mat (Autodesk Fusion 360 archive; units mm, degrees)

design "version 2" references "dumbell"
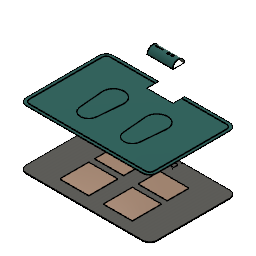
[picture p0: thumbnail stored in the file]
sketch "Sketch1"
  line L1 (808.1915, 45.9253) -> (8.1915, 45.9253)
  line L2 (858.1915, -504.0747) -> (858.1915, -4.0747)
  line L3 (8.1915, -554.0747) -> (808.1915, -554.0747)
  line L4 (-41.8085, -4.0747) -> (-41.8085, -504.0747)
  line L5 (408.1915, -554.0747) -> (408.1915, 45.9253)
  line L6 (858.1915, -254.0747) -> (-41.8085, -254.0747)
  line L7 (258.1915, -554.0747) -> (258.1915, 45.9253)
  line L8 (558.1915, -554.0747) -> (558.1915, 45.9253)
  line L9 (808.1915, 25.2382) -> (8.1915, 25.2382)
  line L10 (-21.1214, -4.0747) -> (-21.1214, -504.0747)
  line L11 (8.1915, -533.3876) -> (808.1915, -533.3876)
  line L12 (837.5044, -504.0747) -> (837.5044, -4.0747)
  arc A1 centre (8.1915, -4.0747) radius 50 clockwise from (-41.8085, -4.0747) to (8.1915, 45.9253)
  arc A2 centre (8.1915, -504.0747) radius 50 clockwise from (8.1915, -554.0747) to (-41.8085, -504.0747)
  arc A3 centre (808.1915, -504.0747) radius 50 clockwise from (858.1915, -504.0747) to (808.1915, -554.0747)
  arc A4 centre (808.1915, -4.0747) radius 50 clockwise from (808.1915, 45.9253) to (858.1915, -4.0747)
  arc A5 centre (808.1915, -4.0747) radius 29.3129 clockwise from (808.1915, 25.2382) to (837.5044, -4.0747)
  arc A6 centre (8.1915, -4.0747) radius 29.3129 clockwise from (-21.1214, -4.0747) to (8.1915, 25.2382)
  arc A7 centre (8.1915, -504.0747) radius 29.3129 clockwise from (8.1915, -533.3876) to (-21.1214, -504.0747)
  arc A8 centre (808.1915, -504.0747) radius 29.3129 clockwise from (837.5044, -504.0747) to (808.1915, -533.3876)
  point P2 (-41.8085, 45.9253)
  point P4 (-41.8085, -554.0747)
  point P3 (858.1915, 45.9253)
  dimension "d1" distance P2 P4 = 600
  dimension "d2" distance P2 P3 = 900
  dimension "d3" distance L4 L7 = 300
  dimension "d4" distance L7 L8 = 300
  dimension "d5" radius A1 = 50
  dimension "d6" radius A2 = 50
  dimension "d7" radius A3 = 50
  dimension "d8" radius A4 = 50
  dimension "d180" = 20.6871
work_plane "WorkPlane2" sketch "Sketch1" AlongDistance 10
sketch "Sketch3" plane through (408.1915, -254.0747, 10) normal (0, 0, 1) x axis (1, 0, 0)
  line L1 (-450, 250) -> (-450, -250)
  line L2 (400, 300) -> (-400, 300)
  line L3 (450, -250) -> (450, 250)
  line L4 (-400, -300) -> (400, -300)
  line L5 (0, -300) -> (0, 300)
  line L6 (90, 300) -> (-90, 300)
  line L7 (90, 220) -> (90, 300)
  line L8 (-90, 220) -> (90, 220)
  line L9 (-90, 300) -> (-90, 220)
  line L10 (90, 260) -> (-90, 260)
  line L11 (-41.3, 265) -> (-75, 265)
  line L12 (-41.3, 233) -> (-41.3, 265)
  line L13 (-75, 233) -> (-41.3, 233)
  line L14 (-75, 265) -> (-75, 233)
  line L15 (-37.7, 288.3) -> (-75, 288.3)
  line L16 (-37.7, 272) -> (-37.7, 288.3)
  line L17 (-75, 272) -> (-37.7, 272)
  line L18 (-75, 288.3) -> (-75, 272)
  line L19 (10.4, 265) -> (-21.3, 265)
  line L20 (10.4, 240.5) -> (10.4, 265)
  line L21 (-21.3, 240.5) -> (10.4, 240.5)
  line L22 (-21.3, 265) -> (-21.3, 240.5)
  line L23 (73, 240.5) -> (49.3, 240.5)
  line L24 (73, 272.5) -> (73, 240.5)
  line L25 (49.3, 272.5) -> (73, 272.5)
  line L26 (49.3, 240.5) -> (49.3, 272.5)
  arc A1 centre (-400, 250) radius 50 clockwise from (-450, 250) to (-400, 300)
  arc A2 centre (400, 250) radius 50 clockwise from (400, 300) to (450, 250)
  arc A3 centre (400, -250) radius 50 clockwise from (450, -250) to (400, -300)
  arc A4 centre (-400, -250) radius 50 clockwise from (-400, -300) to (-450, -250)
  point P24 (-90, 300)
  point P27 (-90, 220)
  point P30 (-75, 265)
  point P33 (-75, 233)
  point P34 (-75, 288.3)
  point P37 (-75, 272)
  point P35 (-37.7, 288.3)
  point P42 (49.3, 240.5)
  point P43 (73, 240.5)
  point P26 (90, 220)
  dimension "d19" distance P24 P27 = 80
  dimension "d21" distance L5 L7 = 90 (= "d38 / 2")
  dimension "d23" distance P30 P33 = 32
  dimension "d25" distance L8 L13 = 13
  dimension "d26" distance P34 P37 = 16.3
  dimension "d27" distance P34 P35 = 37.3
  dimension "d28" distance L11 L17 = 7
  dimension "d31" distance L12 L22 = 20
  dimension "d32" distance P42 P43 = 23.7
  dimension "d38" distance P26 P27 = 180
extrude "Extrude1" new body sketch "Sketch1" profile of L1 L2 L3 L4 A1 A2 A3 A4 blind -3
work_plane "WorkPlane3" sketch "Sketch3" AlongDistance 100
sketch "Sketch4" plane through (408.1915, 5.9253, 110) normal (0, 0, 1) x axis (1, 0, 0)
  line L1 (-90, -40) -> (90, -40)
  line L2 (90, -40) -> (90, 40)
  line L3 (-90, 40) -> (-90, -40)
  line L4 (90, 40) -> (-90, 40)
  line L5 (-75, -27) -> (-41.3, -27)
  line L6 (-75, 5) -> (-75, -27)
  line L7 (-75, 28.3) -> (-75, 12)
  line L8 (-37.7, 28.3) -> (-75, 28.3)
  line L9 (49.3, 12.5) -> (73, 12.5)
  line L10 (73, 12.5) -> (73, -19.5)
  line L11 (73, -19.5) -> (49.3, -19.5)
  line L12 (90, -40) -> (90, -30)
  line L13 (90, 40) -> (-90, 40)
  line L14 (90, -40) -> (90, 40)
  line L15 (-90, -40) -> (90, -40)
  line L16 (-90, 40) -> (-90, -40)
  point P24 (90, -30)
  point P25 (90, -40)
  dimension "d42" distance P24 P25 = 10
extrude "Extrude4" new body sketch "Sketch4" profile of L1 L2 L3 L4 L12 L13 L14 L15 L16 along normal blind 52
work_plane "WorkPlane6" AlongDistance 0
sketch "Sketch6" plane through (498.1915, 5.9253, 136) normal (1, 0, 0) x axis (0, 1, 0)
  line L1 (40, -26) -> (-40, -26)
  line L2 (-40, 16) -> (-40, -26)
  line L3 (40, 26) -> (-40, 26)
  line L4 (0, 26) -> (-30, 26)
  line L5 (0, 26) -> (-40, 26)
  line L6 (0, 0) -> (0, 26)
  line L7 (0, -26) -> (0, 0)
  line L8 (0, 41.2767) -> (0, 26)
  line L9 (-56.7177, 41.2767) -> (0, 41.2767)
  line L10 (-56.7177, -21.9463) -> (-56.7177, 41.2767)
  line L11 (-40, -26) -> (-56.7177, -21.9463)
  line L12 (0, 26) -> (30, 26)
  line L13 (0, 41.2767) -> (0, 26)
  line L14 (40, 16) -> (40, -26)
  line L15 (-37, 16) -> (-37, -19.9995)
  line L16 (0, 23) -> (-30, 23)
  line L17 (0, -26) -> (0, 23)
  line L18 (-28.923, -19.9997) -> (-37, -19.9995)
  line L19 (0, 23) -> (30, 23)
  line L20 (37, 16) -> (37, -19.9995)
  line L21 (28.923, -19.9997) -> (37, -19.9995)
  line L22 (-15, -19) -> (-15, 26)
  line L23 (-28.923, -22.9997) -> (-28.923, -19.9997)
  line L24 (-40, -22.9997) -> (-28.923, -22.9997)
  line L25 (28.923, -22.9997) -> (28.923, -19.9997)
  line L26 (40, -22.9997) -> (28.923, -22.9997)
  line L27 (-40, -22.9997) -> (-40, -26)
  line L28 (45.6639, -22.9997) -> (-40, -22.9997)
  arc A1 centre (-30, 16) radius 10 clockwise from (-40, 16) to (-30, 26)
  arc A2 centre (30, 16) radius 10 clockwise from (30, 26) to (40, 16)
  arc A3 centre (-30, 16) radius 7 clockwise from (-37, 16) to (-30, 23)
  arc A4 centre (30, 16) radius 7 clockwise from (30, 23) to (37, 16)
  point P40 (-15, 26)
  point P41 (-15, -19)
  point P33 (-28.923, -19.9997)
  point P42 (-28.923, -22.9997)
  point P39 (28.923, -19.9997)
  point P44 (28.923, -22.9997)
  dimension "d53" radius A1 = 10
  dimension "d91" distance P40 P41 = 45
  dimension "d93" distance P33 P42 = 3
  dimension "d94" distance P39 P44 = 3
extrude "Extrude15" cut sketch "Sketch6" profile of L2 L3 L4 L5 A1 L8 L9 L10 L11 L13 L27 against normal blind 180
extrude "Extrude10" cut sketch "Sketch6" profile of L1 L6 L7 L15 A3 L16 L17 L18 against normal blind 180
extrude "Extrude8" cut sketch "Sketch6" profile of L1 L6 L7 L15 A3 L16 L17 against normal blind 180
extrude "Extrude6" cut sketch "Sketch6" profile of L2 L3 L4 L5 A1 L8 L9 L10 L11 L13 against normal blind 180
extrude "Extrude7" cut sketch "Sketch6" profile of L3 L8 A2 L12 L13 L14 against normal blind 180
extrude "Extrude9" cut sketch "Sketch6" profile of L1 L6 L7 L17 against normal blind 180
extrude "Extrude11" cut sketch "Sketch6" profile of L1 L6 L7 L17 L19 A4 L20 L21 against normal blind 180
extrude "Extrude12" add sketch "Sketch6" profile of L1 L6 L7 L15 A3 L16 L17 L18 against normal blind 3
extrude "Extrude13" add sketch "Sketch6" profile of L1 L6 L7 L17 L19 A4 L20 L21 against normal blind 3
work_plane "WorkPlane7" AlongDistance 0
sketch "Sketch8" plane through (408.1915, -34.0747, 131) normal (0, -1, 0) x axis (1, 0, 0)
  line L1 (90, 31) -> (-90, 31)
  line L2 (0, 31) -> (0, -21)
work_plane "WorkPlane9" AlongDistance 0
sketch "Sketch10" plane through (318.1915, 5.9253, 136) normal (-1, 0, 0) x axis (0, 1, 0)
  line L1 (0, -23) -> (30, -23)
  line L2 (37, -16) -> (37, 19.9995)
  line L3 (28.923, 19.9997) -> (37, 19.9995)
  line L4 (29.1155, 26) -> (29, 23.0002)
  line L5 (40, 26) -> (-40, 26)
  line L6 (-40, 26) -> (40, 26)
  line L7 (0, 26) -> (0, -23)
  line L8 (0, -23) -> (-30, -23)
  line L9 (-37, -16) -> (-37, 19.9995)
  line L10 (-28.923, 19.9997) -> (-37, 19.9995)
  line L11 (-29.1155, 26) -> (-29, 23.0002)
  arc A1 centre (30, -16) radius 7 clockwise from (37, -16) to (30, -23)
  arc A2 centre (-30, -16) radius 7 clockwise from (-30, -23) to (-37, -16)
extrude "Extrude14" add sketch "Sketch10" against normal blind 3
extrude "Extrude16" cut sketch "Sketch6" profile of L1 L2 L7 L17 L24 L27 L28 against normal blind 180
extrude "Extrude17" cut sketch "Sketch6" profile of L1 L7 L14 L17 L26 L28 against normal blind 180
work_plane "WorkPlane10" AlongDistance 0
sketch "Sketch11" plane through (408.1915, 5.9253, 162) normal (0, 0, 1) x axis (1, 0, 0)
  line L1 (-87, 28.923) -> (87, 28.923)
  line L2 (-87, -28.923) -> (87, -28.923)
  line L3 (10, -28.923) -> (10, 0)
  line L4 (55, 10) -> (10, 10)
  line L5 (55, 0) -> (55, 10)
  line L6 (10, -10) -> (10, 0)
  line L7 (55, -10) -> (10, -10)
  line L8 (55, 0) -> (55, -10)
  line L9 (55, 10) -> (10, -10)
  line L10 (45.65, 0) -> (45.65, 10)
  line L11 (10, 0) -> (10, 10)
  line L12 (90, 30) -> (90, -30)
  curve K1 (-22.2655, -2.3476) -> (-71.7772, -2.3476)
  curve K2 (-22.2655, 5.6524) -> (-22.2655, -2.3476)
  curve K3 (-71.7772, 5.6524) -> (-22.2655, 5.6524)
  curve K4 (-71.7772, -2.3476) -> (-71.7772, 5.6524)
  circle C1 centre (45.65, 0) radius 8
  circle C2 centre (19.6, 0) radius 8
  circle C3 centre (19.6, 0) radius 9
  circle C4 centre (45.65, 0) radius 9
  point P3 (10, 0)
  point P9 (10, 10)
  point P10 (55, 10)
  point P16 (45.65, 10)
  point P19 (19.6, 0)
  dimension "d103" distance P3 P9 = 10
  dimension "d104" distance P9 P10 = 45
  dimension "d107" distance P10 P16 = 9.35
  dimension "d109" diameter C1 = 16
  dimension "d110" distance P3 P19 = 9.6
  dimension "d111" diameter C2 = 16
  dimension "d123" = 1
  dimension "d124" = 1
  dimension "d145" distance L5 L12 = 35
sketch "Sketch12" plane through (498.1915, 5.9253, 136) normal (1, 0, 0) x axis (0, 1, 0)
  line L1 (-24, 26) -> (0, 26)
  line L2 (-24, 24) -> (-24, 26)
  line L3 (0, 23) -> (-30, 23)
  line L4 (0, 26) -> (0, 23)
  line L5 (0, -11.9111) -> (0, 26)
  line L6 (24, 26) -> (0, 26)
  line L7 (24, 24) -> (24, 26)
  line L8 (0, 23) -> (-16.9756, 23)
  line L9 (-17, 24) -> (-24, 24)
  line L10 (-16.9756, 23) -> (-17, 24)
  line L11 (17, 24) -> (24, 24)
  line L12 (24, 24) -> (24, 26)
  line L13 (24, 26) -> (0, 26)
  line L14 (0, 26) -> (0, 23)
  line L15 (0, 23) -> (16.9756, 23)
  line L16 (0, 23) -> (0, 26)
  line L17 (16.9756, 23) -> (17, 24)
  line L18 (0, 23) -> (16.9756, 23)
  point P3 (0, 26)
  point P4 (-24, 26)
  point P5 (-24, 24)
  point P17 (-17, 24)
  dimension "d112" distance P3 P4 = 24
  dimension "d113" distance P4 P5 = 2
  dimension "d115" distance P5 P17 = 7
extrude "Extrude19" cut sketch "Sketch12" against normal blind 180
work_plane "WorkPlane11" sketch "Sketch6" AlongDistance 0
sketch "Sketch13" plane through (498.1915, 25.9253, 137.5002) normal (1, 0, 0) x axis (0, 1, 0)
  line L1 (-37, 22.4998) -> (-44, 22.4998)
  line L2 (-44, 22.4998) -> (-44, 24.4998)
  line L3 (-36.9756, 21.4998) -> (-37, 22.4998)
  line L4 (-3.0244, 21.4998) -> (-36.9756, 21.4998)
  line L5 (-3, 22.4998) -> (-3.0244, 21.4998)
  line L6 (4, 22.4998) -> (-3, 22.4998)
  line L7 (4, 24.4998) -> (4, 22.4998)
  line L8 (-44, 24.4998) -> (4, 24.4998)
extrude "Extrude20" new body sketch "Sketch13" against normal blind 180
extrude "Extrude21" cut sketch "Sketch11" profile of C3 C4 along normal blind 5 and against normal blind 5
work_plane "WorkPlane12" AlongDistance 0
sketch "Sketch14" plane through (408.1915, 5.9253, 162) normal (0, 0, 1) x axis (1, 0, 0)
  line L1 (90, 24) -> (-90, 24)
  line L2 (-90, -24) -> (90, -24)
  line L3 (0, -24) -> (0, 24)
  line L4 (0, 0) -> (-90, 0)
  circle C1 centre (-80, -20.5) radius 2
  circle C2 centre (80, -20.5) radius 2
  circle C3 centre (-80, 20.5) radius 2
  circle C4 centre (80, 20.5) radius 2
  dimension "d132" diameter C1 = 4
extrude "Extrude22" cut sketch "Sketch14" profile of C1 C2 C3 C4 along normal blind 7 and against normal blind 7
work_plane "WorkPlane13" AlongDistance 0
sketch "Sketch15" plane through (408.1915, 5.9253, 113.0003) normal (0, 0, -1) x axis (1, 0, 0)
  line L1 (-87, 28.923) -> (87, 28.923)
  line L2 (-87, 35.923) -> (-87, 28.923)
  line L3 (87, 35.923) -> (-87, 35.923)
  line L4 (0, 28.923) -> (0, 35.923)
  line L5 (77, 35.923) -> (87, 35.923)
  line L6 (77, 28.923) -> (77, 35.923)
  line L7 (87, 28.923) -> (77, 28.923)
  line L8 (87, 35.923) -> (87, 28.923)
  line L9 (-90, 0) -> (-90, -30)
  line L10 (-90, 0) -> (90, 0)
  circle C1 centre (77, 32.423) radius 2
  circle C2 centre (-77, 32.423) radius 2
  circle C3 centre (0, 32.423) radius 2
  circle C4 centre (77, -32.423) radius 2
  circle C5 centre (0, -32.423) radius 2
  circle C6 centre (-77, -32.423) radius 2
  point P2 (87, 28.923)
  point P5 (87, 35.923)
  dimension "d138" distance P2 P5 = 7
  dimension "d140" diameter C1 = 4
  dimension "d141" diameter C3 = 4
extrude "Extrude23" cut sketch "Sketch15" profile of C1 C2 C3 C4 C5 C6 distance 10
work_plane "WorkPlane14" AlongDistance 0
sketch "Sketch16" plane through (408.1915, 42.9253, 134.0003) normal (0, -1, 0) x axis (1, 0, 0)
  line L1 (90, 17.9997) -> (-90, 17.9997)
  line L2 (90, -20.9999) -> (90, 17.9997)
  line L3 (-90, -20.9999) -> (90, -20.9999)
  line L4 (-90, 17.9997) -> (-90, -20.9999)
  line L5 (4, 4.9682) -> (64, 4.9682)
  line L6 (4, 1.9682) -> (4, 4.9682)
  line L7 (64, 1.9682) -> (4, 1.9682)
  line L8 (64, 4.9682) -> (64, 1.9682)
  point P8 (64, 4.9682)
  point P9 (4, 4.9682)
  dimension "d147" distance P8 P9 = 60
  dimension "d148" distance L2 P8 = 26
  dimension "d202" distance L5 L7 = 3
  dimension "d203" distance L3 L7 = 22.9682
extrude "Extrude25" add sketch "Sketch16" profile of L5 L6 L7 L8 to an object
extrude "Extrude24" add sketch "Sketch16" profile of L5 L6 L7 L8 along normal blind 74
work_plane "WorkPlane15" AlongDistance 0
sketch "Sketch17" plane through (442.1915, 5.9253, 138.9685) normal (0, 0, 1) x axis (1, 0, 0)
  line L1 (21, 10) -> (-24, 10)
  line L2 (21, -10) -> (21, 10)
  line L3 (-24, -10) -> (21, -10)
  line L4 (-24, 10) -> (-24, -10)
  line L5 (7, 10.0883) -> (-8, 10.0883)
  line L6 (7, 5.0883) -> (7, 10.0883)
  line L7 (-8, 5.0883) -> (7, 5.0883)
  line L8 (-8, 10.0883) -> (-8, 5.0883)
  line L9 (-24, 0) -> (-24, 10)
  line L10 (21, 10) -> (-24, 10)
  point P8 (-8, 10.0883)
  point P9 (7, 10.0883)
  point P11 (-8, 5.0883)
  dimension "d154" distance P8 P9 = 15
  dimension "d155" distance P8 P11 = 5
  dimension "d156" distance L8 L9 = 16
extrude "Extrude26" cut sketch "Sketch17" profile of L1 L6 L7 L8 L10 along normal blind 10 and against normal blind 10
work_plane "WorkPlane16" AlongDistance 0
sketch "Sketch18" plane through (0, 0, 138.9685) normal (0, 0, 1) x axis (1, 0, 0)
sketch "Sketch19" plane through (318.1915, 5.9253, 137.5002) normal (-1, 0, 0) x axis (0, 1, 0)
work_plane "WorkPlane17" AlongDistance 0
sketch "Sketch20" plane through (408.1915, 5.9253, 113.0003) normal (0, 0, -1) x axis (1, 0, 0)
  line L1 (-75, -5) -> (-75, 27)
  line L2 (-41.3, -5) -> (-75, -5)
  line L3 (-41.3, 27) -> (-41.3, -5)
  line L4 (-75, 27) -> (-41.3, 27)
sketch "Sketch21" plane through (408.1915, 5.9253, 113.0003) normal (0, 0, -1) x axis (1, 0, 0)
  line L1 (-41.3, -5) -> (-75, -5)
  line L2 (-41.3, 27) -> (-41.3, -5)
  line L3 (-75, 27) -> (-41.3, 27)
  line L4 (-75, -5) -> (-75, 27)
extrude "Extrude27" new body sketch "Sketch21" against normal blind 10
work_plane "WorkPlane18" AlongDistance 0
sketch "Sketch23" plane through (318.1915, 5.9253, 137.5002) normal (-1, 0, 0) x axis (0, 1, 0)
  line L1 (-16.923, 24.4998) -> (-28.923, 24.4998)
  line L2 (-16.923, 14.4998) -> (-16.923, 24.4998)
  line L3 (-28.923, 14.4998) -> (-16.923, 14.4998)
  line L4 (-28.923, 24.4998) -> (-28.923, 14.4998)
  point P2 (-28.923, 24.4998)
  point P3 (-16.923, 24.4998)
  point P5 (-28.923, 14.4998)
  dimension "d167" distance P2 P3 = 12
  dimension "d168" distance P2 P5 = 10
extrude "Extrude28" cut sketch "Sketch23" along normal blind 5 and against normal blind 5
work_plane "WorkPlane19"
split "Split1"
move "Move1"
work_plane "WorkPlane20" AlongDistance 0
sketch "Sketch24" plane through (408.1915, -254.0747, -3) normal (0, 0, -1) x axis (1, 0, 0)
  line L1 (400, 300) -> (-400, 300)
  line L2 (450, -250) -> (450, 250)
  line L3 (-400, -300) -> (400, -300)
  line L4 (-450, 250) -> (-450, -250)
  arc A1 centre (-400, 250) radius 50 clockwise from (-450, 250) to (-400, 300)
  arc A2 centre (400, 250) radius 50 clockwise from (400, 300) to (450, 250)
  arc A3 centre (400, -250) radius 50 clockwise from (450, -250) to (400, -300)
  arc A4 centre (-400, -250) radius 50 clockwise from (-400, -300) to (-450, -250)
  dimension "d174" radius A1 = 50
  dimension "d175" radius A2 = 50
  dimension "d176" radius A3 = 50
  dimension "d177" radius A4 = 50
extrude "Extrude29" add of existing geometry blind 3
sketch "Sketch22"
copy_paste_bodies "CopyPasteBodies1"
move "Move2"
move "Move3"
work_plane "WorkPlane21" AlongDistance 0
sketch "Sketch25" plane through (408.1915, -254.0747, 0) normal (0, 0, 1) x axis (1, 0, 0)
  line L1 (90, 300) -> (-90, 300)
  line L2 (90, 220) -> (90, 300)
  line L3 (-90, 220) -> (90, 220)
  line L4 (-90, 300) -> (-90, 220)
  line L5 (90, 300) -> (-90, 300)
  line L6 (90, 220) -> (90, 300)
  line L7 (-90, 220) -> (90, 220)
  line L8 (-90, 300) -> (-90, 220)
extrude "Extrude30" new body sketch "Sketch3" profile of L1 A1 L2 A2 L3 A3 L4 A4 L7 L8 L9 against normal blind 3
move "Move4"
work_plane "WorkPlane22" AlongDistance -3
sketch "Sketch26" plane through (408.1915, -254.0747, -5) normal (0, 0, 1) x axis (1, 0, 0)
  line L1 (400, -300) -> (-400, -300)
  line L2 (450, 250) -> (450, -250)
  line L3 (-400, 300) -> (400, 300)
  line L4 (-450, -250) -> (-450, 250)
  line L5 (400, -280) -> (-400, -280)
  line L6 (430, 250) -> (430, -250)
  line L7 (-430, -250) -> (-430, 250)
  line L8 (90, 280) -> (400, 280)
  line L9 (-400, 280) -> (-90, 280)
  line L10 (90, 278) -> (400, 278)
  line L11 (428, 250) -> (428, -250)
  line L12 (400, -278) -> (-400, -278)
  line L13 (-428, -250) -> (-428, 250)
  line L14 (-400, 278) -> (-92, 278)
  line L15 (-90, 278) -> (-90, 280)
  line L16 (-92, 278) -> (-90, 278)
  line L17 (90, 278) -> (90, 280)
  arc A1 centre (-400, 250) radius 50 clockwise from (-450, 250) to (-400, 300)
  arc A2 centre (400, 250) radius 50 clockwise from (400, 300) to (450, 250)
  arc A3 centre (400, -250) radius 50 clockwise from (450, -250) to (400, -300)
  arc A4 centre (-400, -250) radius 50 clockwise from (-400, -300) to (-450, -250)
  arc A5 centre (-400, -250) radius 30 clockwise from (-400, -280) to (-430, -250)
  arc A6 centre (400, -250) radius 30 clockwise from (430, -250) to (400, -280)
  arc A7 centre (400, 250) radius 30 clockwise from (400, 280) to (430, 250)
  arc A8 centre (-400, 250) radius 30 clockwise from (-430, 250) to (-400, 280)
  arc A9 centre (400, 250) radius 28 clockwise from (400, 278) to (428, 250)
  arc A10 centre (400, -250) radius 28 clockwise from (428, -250) to (400, -278)
  arc A11 centre (-400, -250) radius 28 clockwise from (-400, -278) to (-428, -250)
  arc A12 centre (-400, 250) radius 28 clockwise from (-428, 250) to (-400, 278)
  dimension "d185" radius A1 = 50
  dimension "d186" radius A2 = 50
  dimension "d187" radius A3 = 50
  dimension "d188" radius A4 = 50
extrude "Extrude31" cut sketch "Sketch26" profile of A7 A5 A8 L5 A6 L6 L9 L7 A9 L10 L13 L11 A10 A11 A12 L12 L14 L15 L16 L17 along normal blind 1
move "Move5"
work_plane "WorkPlane26" AlongDistance 0
sketch "Sketch30" plane through (408.1915, 5.9253, 49) normal (0, 0, 1) x axis (1, 0, 0)
  line L1 (10.4, -19.5) -> (10.4, 5)
  line L2 (10.6, 0) -> (-90, 0)
  curve K1 (-5.099, -3.4674) -> (-73.512, -3.4674)
  curve K2 (-5.099, 6.5326) -> (-5.099, -3.4674)
  curve K3 (-73.512, 6.5326) -> (-5.099, 6.5326)
  curve K4 (-73.512, -3.4674) -> (-73.512, 6.5326)
extrude "Extrude33" add sketch "Sketch30" along normal blind 1.2
work_plane "WorkPlane27" AlongDistance 0
sketch "Sketch31" plane through (408.1915, -254.0747, -5) normal (0, 0, 1) x axis (1, 0, 0)
  line L1 (-37.7, 288.3) -> (-75, 288.3)
  line L2 (-75, 288.3) -> (-75, 272)
  line L3 (-75, 272) -> (-37.7, 272)
  line L4 (-37.7, 272) -> (-37.7, 288.3)
  line L5 (-41.3, 233) -> (-41.3, 265)
  line L6 (-41.3, 265) -> (-75, 265)
  line L7 (-75, 265) -> (-75, 233)
  line L8 (-75, 233) -> (-41.3, 233)
  line L9 (-21.3, 240.5) -> (10.4, 240.5)
  line L10 (-21.3, 265) -> (-21.3, 240.5)
  line L11 (10.4, 265) -> (-21.3, 265)
  line L12 (10.4, 240.5) -> (10.4, 265)
  line L13 (49.3, 240.5) -> (49.3, 272.5)
  line L14 (49.3, 272.5) -> (73, 272.5)
  line L15 (73, 272.5) -> (73, 240.5)
  line L16 (73, 240.5) -> (49.3, 240.5)
  line L17 (-90, 300) -> (-90, 220)
  line L18 (-90, 220) -> (90, 220)
  line L19 (90, 220) -> (90, 300)
  line L20 (-450, 250) -> (-450, -250)
  line L21 (450, -250) -> (450, 250)
  line L22 (450, 0) -> (-450, 0)
  line L23 (400, 300) -> (-400, 300)
  line L24 (-400, -300) -> (400, -300)
  line L25 (-150, -300) -> (-150, 300)
  line L26 (150, -300) -> (150, 300)
  line L27 (-50, 170) -> (-250, 170)
  line L28 (-50, 20) -> (-50, 170)
  line L29 (-250, 20) -> (-50, 20)
  line L30 (-250, 170) -> (-250, 20)
  line L31 (-250, -20) -> (-50, -20)
  line L32 (-250, -170) -> (-250, -20)
  line L33 (-50, -20) -> (-50, -170)
  line L34 (-250, -220) -> (-250, -170)
  line L35 (-50, -220) -> (-250, -220)
  line L36 (-50, -170) -> (-50, -220)
  line L37 (0, -300) -> (0, 0)
  line L38 (250, 170) -> (250, 20)
  line L39 (50, 170) -> (250, 170)
  line L40 (50, 20) -> (50, 170)
  line L41 (250, 20) -> (50, 20)
  line L42 (250, -20) -> (50, -20)
  line L43 (250, -170) -> (250, -20)
  line L44 (250, -220) -> (250, -170)
  line L45 (50, -220) -> (250, -220)
  line L46 (50, -170) -> (50, -220)
  line L47 (50, -20) -> (50, -170)
  circle C1 centre (-77, 227.577) radius 2
  circle C2 centre (0, 227.577) radius 2
  circle C3 centre (77, 292.423) radius 2
  circle C4 centre (0, 292.423) radius 2
  circle C5 centre (-77, 292.423) radius 2
  circle C6 centre (77, 227.577) radius 2
  point P60 (-250, 170)
  point P61 (-50, 170)
  point P63 (-250, 20)
  point P66 (-250, -170)
  point P68 (-250, -220)
  dimension "d212" distance L20 L25 = 300
  dimension "d213" distance L21 L26 = 300
  dimension "d214" distance P60 P61 = 200
  dimension "d215" distance P60 P63 = 150
  dimension "d216" distance L22 L29 = 20
  dimension "d217" distance L25 L28 = 100
  dimension "d219" distance P66 P68 = 50
extrude "Extrude35" cut sketch "Sketch31" profile of C1 C2 C3 C4 C5 C6 distance 10
extrude "Extrude34" cut sketch "Sketch31" profile of L1 L2 L3 L4 L5 L6 L7 L8 L9 L10 L11 L12 L13 L14 L15 L16 against normal blind 1
extrude "Extrude36" cut sketch "Sketch31" profile of L27 L28 L29 L30 L31 L32 L33 L34 L35 L36 L38 L39 L40 L41 L42 L43 L44 L45 L46 L47 against normal blind 1
extrude "Extrude37" new body sketch "Sketch31" profile of L27 L28 L29 L30 L31 L32 L33 L34 L35 L36 L38 L39 L40 L41 L42 L43 L44 L45 L46 L47 along normal blind 1
move "Move6"
work_plane "WorkPlane28" AlongDistance 0
sketch "Sketch32" plane through (408.1915, -254.0747, -3) normal (0, 0, 1) x axis (1, 0, 0)
  line L1 (-250, -170) -> (-250, -20)
  line L2 (-250, -20) -> (-50, -20)
  line L3 (-50, -20) -> (-50, -170)
  line L4 (-50, -170) -> (-50, -220)
  line L5 (-50, -220) -> (-250, -220)
  line L6 (-250, -220) -> (-250, -170)
  line L7 (-250, 170) -> (-250, 20)
  line L8 (-50, 170) -> (-250, 170)
  line L9 (-50, 20) -> (-50, 170)
  line L10 (-250, 20) -> (-50, 20)
  line L11 (50, 20) -> (50, 170)
  line L12 (50, 170) -> (250, 170)
  line L13 (250, 170) -> (250, 20)
  line L14 (250, 20) -> (50, 20)
  line L15 (250, -20) -> (50, -20)
  line L16 (50, -20) -> (50, -170)
  line L17 (50, -170) -> (50, -220)
  line L18 (50, -220) -> (250, -220)
  line L19 (250, -220) -> (250, -170)
  line L20 (250, -170) -> (250, -20)
  line L21 (-150, -220) -> (-150, 170)
  line L22 (150, -220) -> (150, 170)
  line L23 (-50, 20) -> (-250, 170)
  line L24 (-50, -220) -> (-250, -20)
  line L25 (-150, 50) -> (-150, 20)
  line L26 (-207.775, -125.1034) -> (-222.4583, 41.1235)
  line L27 (-92.226, -125.115) -> (-77.387, 42.4932)
  line L28 (-90, 220) -> (90, 220)
  line L29 (-400, -280) -> (400, -280)
  line L30 (0, -280) -> (0, 220)
  line L31 (207.775, -125.1034) -> (222.4583, 41.1235)
  line L32 (92.226, -125.115) -> (77.387, 42.4932)
  line L33 (-91.7279, -125.159) -> (-76.8893, 42.4455)
  line L34 (-208.2731, -125.1474) -> (-222.9556, 41.0711)
  line L35 (207.775, -125.1034) -> (222.4583, 41.1235)
  line L36 (92.226, -125.115) -> (77.387, 42.4932)
  line L37 (92.226, -125.115) -> (77.387, 42.4932)
  line L38 (207.775, -125.1034) -> (222.4583, 41.1235)
  line L39 (207.277, -125.0594) -> (221.961, 41.1759)
  line L40 (92.724, -125.0709) -> (77.8847, 42.541)
  arc A1 centre (-150, -120) radius 58 clockwise from (-92.226, -125.115) to (-207.775, -125.1034)
  arc A2 centre (-150, 50) radius 73 clockwise from (-222.4583, 41.1235) to (-77.387, 42.4932)
  arc A3 centre (150, 50) radius 73 clockwise from (77.387, 42.4932) to (222.4583, 41.1235)
  arc A4 centre (150, -120) radius 58 clockwise from (207.775, -125.1034) to (92.226, -125.115)
  arc A5 centre (-150, -120) radius 58.5 clockwise from (-91.7279, -125.159) to (-208.2731, -125.1474)
  arc A6 centre (-150, 50) radius 73.5 clockwise from (-222.9556, 41.0711) to (-76.8893, 42.4455)
  arc A7 centre (150, 50) radius 73 clockwise from (77.387, 42.4932) to (222.4583, 41.1235)
  arc A8 centre (150, -120) radius 58 clockwise from (207.775, -125.1034) to (92.226, -125.115)
  arc A9 centre (150, 50) radius 73 clockwise from (77.387, 42.4932) to (222.4583, 41.1235)
  arc A10 centre (150, -120) radius 58 clockwise from (207.775, -125.1034) to (92.226, -125.115)
  arc A11 centre (150, -120) radius 57.5 clockwise from (207.277, -125.0594) to (92.724, -125.0709)
  arc A12 centre (150, 50) radius 72.5 clockwise from (77.8847, 42.541) to (221.961, 41.1759)
  point P50 (-150, 20)
  point P51 (-150, 50)
  dimension "d227" distance P50 P51 = 30
  dimension "d231" = 0.5
  dimension "d234" = 0.5
extrude "Extrude38" cut sketch "Sketch32" profile of L26 A1 L27 A2 A5 L33 A6 L34 against normal blind 1
extrude "Extrude39" cut sketch "Sketch32" profile of A3 L31 L32 A4 A7 L35 L36 A8 L37 A9 L38 A10 A11 L39 A12 L40 against normal blind 1
copy_paste_bodies "CopyPasteBodies2"
move "Move7"
work_plane "WorkPlane29"
split "Split2"
work_plane "WorkPlane30"
split "Split3"
sketch "Sketch37" plane through (408.1915, 0, 0) normal (-1, 0, 0) x axis (0, -1, 0)
  line L1 (-147.888, 40.9454) -> (-147.8635, 39.9454)
  line L2 (-154.888, 40.9454) -> (-147.888, 40.9454)
  line L3 (-154.888, 42.9454) -> (-154.888, 40.9454)
  line L4 (-160.888, 42.9454) -> (-154.888, 42.9454)
  line L5 (-170.888, -6.0543) -> (-170.888, 32.9454)
  line L6 (-165.311, -6.0543) -> (-170.888, -6.0543)
  line L7 (-165.311, -3.0541) -> (-165.311, -6.0543)
  line L8 (-167.888, -3.0541) -> (-165.311, -3.0541)
  line L9 (-167.888, 32.9454) -> (-167.888, -3.0541)
  line L10 (-147.8635, 39.9454) -> (-160.888, 39.9454)
  line L11 (-169.388, -0.0543) -> (-170.888, -0.0543)
  line L12 (-169.388, 5.9457) -> (-169.388, -0.0543)
  line L13 (-170.888, 5.9457) -> (-169.388, 5.9457)
  line L14 (-170.888, -0.0543) -> (-170.888, 5.9457)
  line L15 (-169.388, 26.9457) -> (-170.888, 26.9457)
  line L16 (-169.388, 20.9457) -> (-169.388, 26.9457)
  line L17 (-170.888, 20.9457) -> (-169.388, 20.9457)
  line L18 (-170.888, 26.9457) -> (-170.888, 20.9457)
  arc A1 centre (-160.888, 32.9454) radius 10 clockwise from (-170.888, 32.9454) to (-160.888, 42.9454)
  arc A2 centre (-160.888, 32.9454) radius 7 clockwise from (-167.888, 32.9454) to (-160.888, 39.9454)
  point P15 (-170.888, -0.0543)
  point P18 (-170.888, 5.9457)
  point P16 (-169.388, -0.0543)
  point P19 (-170.888, 26.9457)
  point P22 (-170.888, 20.9457)
  point P20 (-169.388, 26.9457)
  dimension "d258" distance P15 P18 = 6
  dimension "d259" distance P15 P16 = 1.5
  dimension "d260" distance P19 P22 = 6
  dimension "d261" distance P19 P20 = 1.5
  dimension "d262" distance L6 L11 = 6
  dimension "d263" distance L13 L17 = 15
extrude "Extrude44" add sketch "Sketch37" profile of L5 L11 L12 L13 L14 L15 L16 L17 L18 along normal blind 10
sketch "Sketch39" plane through (0, 170.888, 0) normal (0, 1, 0) x axis (-1, 0, 0)
  line L1 (-408.1915, -6.0543) -> (-408.1915, 32.9454)
  line L2 (-318.1915, -6.0543) -> (-408.1915, -6.0543)
  line L3 (-318.1915, 32.9454) -> (-318.1915, -6.0543)
  line L4 (-408.1915, 32.9454) -> (-318.1915, 32.9454)
  line L5 (-397.9915, 26.9457) -> (-408.1915, 26.9457)
  line L6 (-397.9915, 20.9457) -> (-397.9915, 26.9457)
  line L7 (-408.1915, 20.9457) -> (-397.9915, 20.9457)
  line L8 (-408.1915, 26.9457) -> (-408.1915, 20.9457)
  line L9 (-397.9915, 5.9457) -> (-408.1915, 5.9457)
  line L10 (-397.9915, -0.0543) -> (-397.9915, 5.9457)
  line L11 (-408.1915, -0.0543) -> (-397.9915, -0.0543)
  line L12 (-408.1915, 5.9457) -> (-408.1915, -0.0543)
  point P6 (-408.1915, 26.9457)
  point P7 (-397.9915, 26.9457)
  point P9 (-408.1915, 20.9457)
  point P11 (-408.1915, 5.9457)
  point P12 (-397.9915, 5.9457)
  point P14 (-408.1915, -0.0543)
  dimension "d266" distance P6 P7 = 10.2
  dimension "d267" distance P6 P9 = 6
  dimension "d268" distance P11 P12 = 10.2
  dimension "d269" distance P11 P14 = 6
sketch "Sketch40" plane through (408.1915, 0, 0) normal (-1, 0, 0) x axis (0, -1, 0)
  line L1 (-93.888, -3.0541) -> (-93.888, 32.9454)
  line L2 (-96.4649, -3.0541) -> (-93.888, -3.0541)
  line L3 (-96.4649, -6.0543) -> (-96.4649, -3.0541)
  line L4 (-90.888, -6.0543) -> (-96.4649, -6.0543)
  line L5 (-90.888, 32.9454) -> (-90.888, -6.0543)
  line L6 (-106.888, 42.9454) -> (-100.888, 42.9454)
  line L7 (-106.888, 40.9454) -> (-106.888, 42.9454)
  line L8 (-113.888, 40.9454) -> (-106.888, 40.9454)
  line L9 (-113.9124, 39.9454) -> (-113.888, 40.9454)
  line L10 (-100.888, 39.9454) -> (-113.9124, 39.9454)
  line L11 (-92.388, -0.0543) -> (-90.888, -0.0543)
  line L12 (-92.388, 5.9457) -> (-92.388, -0.0543)
  line L13 (-90.888, 5.9457) -> (-92.388, 5.9457)
  line L14 (-90.888, -0.0543) -> (-90.888, 5.9457)
  line L15 (-92.388, 20.9457) -> (-90.888, 20.9457)
  line L16 (-92.388, 26.9457) -> (-92.388, 20.9457)
  line L17 (-90.888, 26.9457) -> (-92.388, 26.9457)
  line L18 (-90.888, 20.9457) -> (-90.888, 26.9457)
  arc A1 centre (-100.888, 32.9454) radius 7 clockwise from (-100.888, 39.9454) to (-93.888, 32.9454)
  arc A2 centre (-100.888, 32.9454) radius 10 clockwise from (-100.888, 42.9454) to (-90.888, 32.9454)
  point P15 (-90.888, -0.0543)
  point P18 (-90.888, 5.9457)
  point P16 (-92.388, -0.0543)
  point P19 (-90.888, 20.9457)
  point P22 (-90.888, 26.9457)
  point P20 (-92.388, 20.9457)
  dimension "d270" distance P15 P18 = 6
  dimension "d271" distance P15 P16 = 1.5
  dimension "d272" distance L4 L11 = 6
  dimension "d273" distance P19 P22 = 6
  dimension "d274" distance P19 P20 = 1.5
  dimension "d275" distance L13 P20 = 15
extrude "Extrude45" add sketch "Sketch40" profile of L5 L11 L12 L13 L14 L15 L16 L17 L18 along normal blind 10
sketch "Sketch41" plane through (0, 90.888, 0) normal (0, -1, 0) x axis (1, 0, 0)
  line L1 (408.1915, 32.9454) -> (408.1915, -6.0543)
  line L2 (318.1915, 32.9454) -> (408.1915, 32.9454)
  line L3 (318.1915, -6.0543) -> (318.1915, 32.9454)
  line L4 (408.1915, -6.0543) -> (318.1915, -6.0543)
  line L5 (397.9915, 20.9457) -> (408.1915, 20.9457)
  line L6 (397.9915, 26.9457) -> (397.9915, 20.9457)
  line L7 (408.1915, 26.9457) -> (397.9915, 26.9457)
  line L8 (408.1915, 20.9457) -> (408.1915, 26.9457)
  line L9 (397.9915, -0.0543) -> (408.1915, -0.0543)
  line L10 (397.9915, 5.9457) -> (397.9915, -0.0543)
  line L11 (408.1915, 5.9457) -> (397.9915, 5.9457)
  line L12 (408.1915, -0.0543) -> (408.1915, 5.9457)
extrude "Extrude46" cut sketch "Sketch41" profile of L1 L5 L6 L7 L8 L9 L10 L11 L12 against normal blind 1.52
work_plane "WorkPlane32" AlongDistance 0
sketch "Sketch43" plane through (448.1915, 90.888, 13.4455) normal (0, -1, 0) x axis (1, 0, 0)
  line L1 (50, -19.4998) -> (50, 26.4998)
  line L2 (50, 19.4998) -> (50, -19.4998)
  line L3 (50, -19.4998) -> (50, -11.9998)
  line L4 (50, -19.4998) -> (50, -11.9998)
  line L5 (42.5, -19.4998) -> (50, -19.4998)
  circle C1 centre (50, -19.4998) radius 7.5
  dimension "d289" diameter C1 = 15
extrude "Extrude47" add sketch "Sketch43" against normal blind 1
sketch "Sketch44" plane through (0, 90.888, 0) normal (0, -1, 0) x axis (1, 0, 0)
  line L1 (408.1915, 26.9457) -> (408.1915, 32.9454)
  line L2 (398.1915, 26.9457) -> (408.1915, 26.9457)
  line L3 (398.1915, 20.9457) -> (398.1915, 26.9457)
  line L4 (408.1915, 20.9457) -> (398.1915, 20.9457)
  line L5 (408.1915, 5.9457) -> (408.1915, 20.9457)
  line L6 (398.1915, 5.9457) -> (408.1915, 5.9457)
  line L7 (398.1915, -0.0543) -> (398.1915, 5.9457)
  line L8 (408.1915, -0.0543) -> (398.1915, -0.0543)
  line L9 (408.1915, -6.0543) -> (408.1915, -0.0543)
  line L10 (490.6915, -6.0543) -> (408.1915, -6.0543)
  line L11 (498.1915, 32.9454) -> (498.1915, 1.4457)
  line L12 (408.1915, 32.9454) -> (498.1915, 32.9454)
  arc A1 centre (498.1915, -6.0543) radius 7.5 clockwise from (498.1915, 1.4457) to (490.6915, -6.0543)
  circle C1 centre (408.1915, -6.0543) radius 7.5
  dimension "d288" diameter C1 = 15
extrude "Extrude48" add sketch "Sketch44" profile of L7 L8 L9 L10 C1 against normal blind 1
sketch "Sketch45" plane through (0, 90.888, 0) normal (0, -1, 0) x axis (1, 0, 0)
  line L1 (408.1915, 26.9457) -> (408.1915, 32.9454)
  line L2 (398.1915, 26.9457) -> (408.1915, 26.9457)
  line L3 (398.1915, 20.9457) -> (398.1915, 26.9457)
  line L4 (408.1915, 20.9457) -> (398.1915, 20.9457)
  line L5 (408.1915, 5.9457) -> (408.1915, 20.9457)
  line L6 (398.1915, 5.9457) -> (408.1915, 5.9457)
  line L7 (490.6915, -6.0543) -> (415.6915, -6.0543)
  line L8 (498.1915, 32.9454) -> (498.1915, 1.4457)
  line L9 (408.1915, 32.9454) -> (498.1915, 32.9454)
  line L10 (398.1915, -0.0543) -> (398.1915, 5.9457)
  line L11 (403.6915, -0.0543) -> (398.1915, -0.0543)
  arc A1 centre (408.1915, -6.0543) radius 7.5 clockwise from (415.6915, -6.0543) to (403.6915, -0.0543)
  arc A2 centre (498.1915, -6.0543) radius 7.5 clockwise from (498.1915, 1.4457) to (490.6915, -6.0543)
  circle C1 centre (498.1915, 25.7411) radius 7.2043
  circle C2 centre (408.1915, 26.9457) radius 5.8309
extrude "Extrude49" add sketch "Sketch45" profile of L1 L2 L8 C1 C2 against normal blind 1
work_plane "WorkPlane33" AlongDistance 0
sketch "Sketch46" plane through (498.1915, -14.0747, 21.5002) normal (1, 0, 0) x axis (0, 1, 0)
  line L1 (3.0244, 21.4998) -> (-10, 21.4998)
  line L2 (-20, -22.5002) -> (-20, -24.5002)
  line L3 (20, 17.4998) -> (20, 17.4998)
  line L4 (60, -24.5002) -> (60, -22.5002)
  line L5 (-20, -24.5002) -> (60, -24.5002)
  arc A1 centre (20, -22.5002) radius 40 clockwise from (-20, -22.5002) to (20, 17.4998)
  arc A2 centre (20, -22.5002) radius 40 clockwise from (20, 17.4998) to (60, -22.5002)
  point P5 (-20, -24.5002)
  point P6 (-20, 17.4998)
  point P7 (60, 17.4998)
  dimension "d291" distance P5 P6 = 42
  dimension "d292" distance P6 P7 = 80
  dimension "d293" radius A1 = 40
  dimension "d294" radius A2 = 40
extrude "Extrude50" new body sketch "Sketch46" profile of L2 L4 L5 A1 A2 against normal blind 3
copy_paste_bodies "CopyPasteBodies3"
move "Move8"
move "Move9"
work_plane "WorkPlane34" AlongDistance 0
sketch "Sketch47" plane through (495.1915, 5.9253, 18) normal (-1, 0, 0) x axis (0, 1, 0)
  line L1 (40, 19) -> (40, 21)
  line L2 (40, 21) -> (40, 19)
  line L3 (0, -21) -> (0, -21)
  line L4 (-40, 21) -> (40, 21)
  line L5 (-40, 21) -> (-40, 19)
  line L6 (39.5, 19) -> (39.5, 21)
  line L7 (-39.5, 21) -> (-39.5, 19)
  arc A1 centre (0, 19) radius 40 clockwise from (40, 19) to (0, -21)
  arc A2 centre (0, 19) radius 40 clockwise from (0, -21) to (-40, 19)
  arc A3 centre (0, 19) radius 39.5 clockwise from (39.5, 19) to (0, -20.5)
  arc A4 centre (0, 19) radius 39.5 clockwise from (0, -20.5) to (-39.5, 19)
  point P3 (40, 21)
  point P4 (40, -21)
  point P7 (-40, -21)
  dimension "d298" distance P3 P4 = 42
  dimension "d299" distance P4 P7 = 80
  dimension "d300" radius A1 = 40
  dimension "d301" radius A2 = 40
  dimension "d302" = 0.5
  dimension "d303" = 0.5
extrude "Extrude51" new body sketch "Sketch47" profile of L1 L2 L4 L5 A1 A2 A3 L6 A4 L7 along normal blind 174
extrude "Extrude52" cut sketch "Sketch11" profile of C3 C4 against normal blind 145
extrude "Extrude53" cut sketch "Sketch11" against normal blind 125
component_insert "Component Insert"
move "Move10"
move "Move11"
move "Move12"
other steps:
base_feature "Base Feature1"
base_feature "Base Feature2"
base_feature "Base Feature3"

design "dumbell"
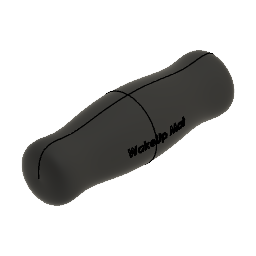
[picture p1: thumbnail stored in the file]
sketch "Sketch1" plane through (0, 0, 0) normal (1, 0, 0) x axis (0, 1, 0)
  line L1 (113.2281, 19.0689) -> (-6.7719, 19.0689)
  line L2 (113.2281, 31.5689) -> (-6.7719, 31.5689)
  line L3 (113.2281, -5.9311) -> (115.2281, -5.9311)
  line L4 (53.2281, 19.0689) -> (53.2281, 44.0689)
  curve K1 (130.7824, 19.0689) -> (53.2281, 44.0689)
  curve K2 (65.3627, 44.0689) -> (41.0935, 44.0689)
  curve K3 (-24.3262, 19.0689) -> (53.2281, 44.0689)
  curve K4 (41.0935, 44.0689) -> (65.3627, 44.0689)
  line L5 (130.7824, 19.0689) -> (-24.3262, 19.0689)
revolve "Revolve2" sketch "Sketch1" AlongAngle 360
work_plane "WorkPlane1" sketch "Sketch1" AlongDistance 55
sketch "Sketch4" plane through (55, 53.2281, 31.5689) normal (1, 0, 0) x axis (0, 1, 0)
  curve K1 (26.8975, -13.7169) -> (-22.6142, -13.7169)
  curve K2 (26.8975, -5.7169) -> (26.8975, -13.7169)
  curve K3 (-22.6142, -5.7169) -> (26.8975, -5.7169)
  curve K4 (-22.6142, -13.7169) -> (-22.6142, -5.7169)
extrude "Extrude3" cut sketch "Sketch4" against normal blind 35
